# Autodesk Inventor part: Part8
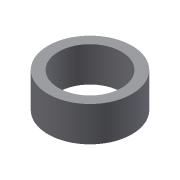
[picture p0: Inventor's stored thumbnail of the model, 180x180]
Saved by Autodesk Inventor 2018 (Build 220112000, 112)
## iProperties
Shininess: 77.0
Length Units: 11269
Angle Units: 11279
Time Units: 11290
Mass Units: 11283
Length Display Precision: 3
Angle Display Precision: 2
Created: 2002-01
Part Number: Part8
Document SubType Name: Modeling
Designer: ***
Density: 1 g/cm^3
Material: Generic
Appearance: Default
Density: 0.0
Volumn: 0.0
Area: 0.0
PropertySet Name: Model Information
Control State: 0
Master: False
Checked Out: False
Author: ***
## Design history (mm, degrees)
sketch "Sketch1"
  geometry: C1 r 30 at (0, 0); C2 r 22.5 at (0, 0)
  constraints: 2 centre point, 1 coincident
  dimensions: "d0" = 60 diameter of C1; "d1" = 45 diameter of C2
extrude "Extrusion1" new body sketch "Sketch1" distance "d2" = 25; taper "d3" = 0 deg
body "Solid1"
